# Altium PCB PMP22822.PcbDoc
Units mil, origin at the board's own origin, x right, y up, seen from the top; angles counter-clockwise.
Board outline 2785.43 x 1948.82 mil, 2 copper layers (Top Layer, Bottom Layer), stack 62 mil thick; 55 components, 24 nets, 111 pads, 31 vias.
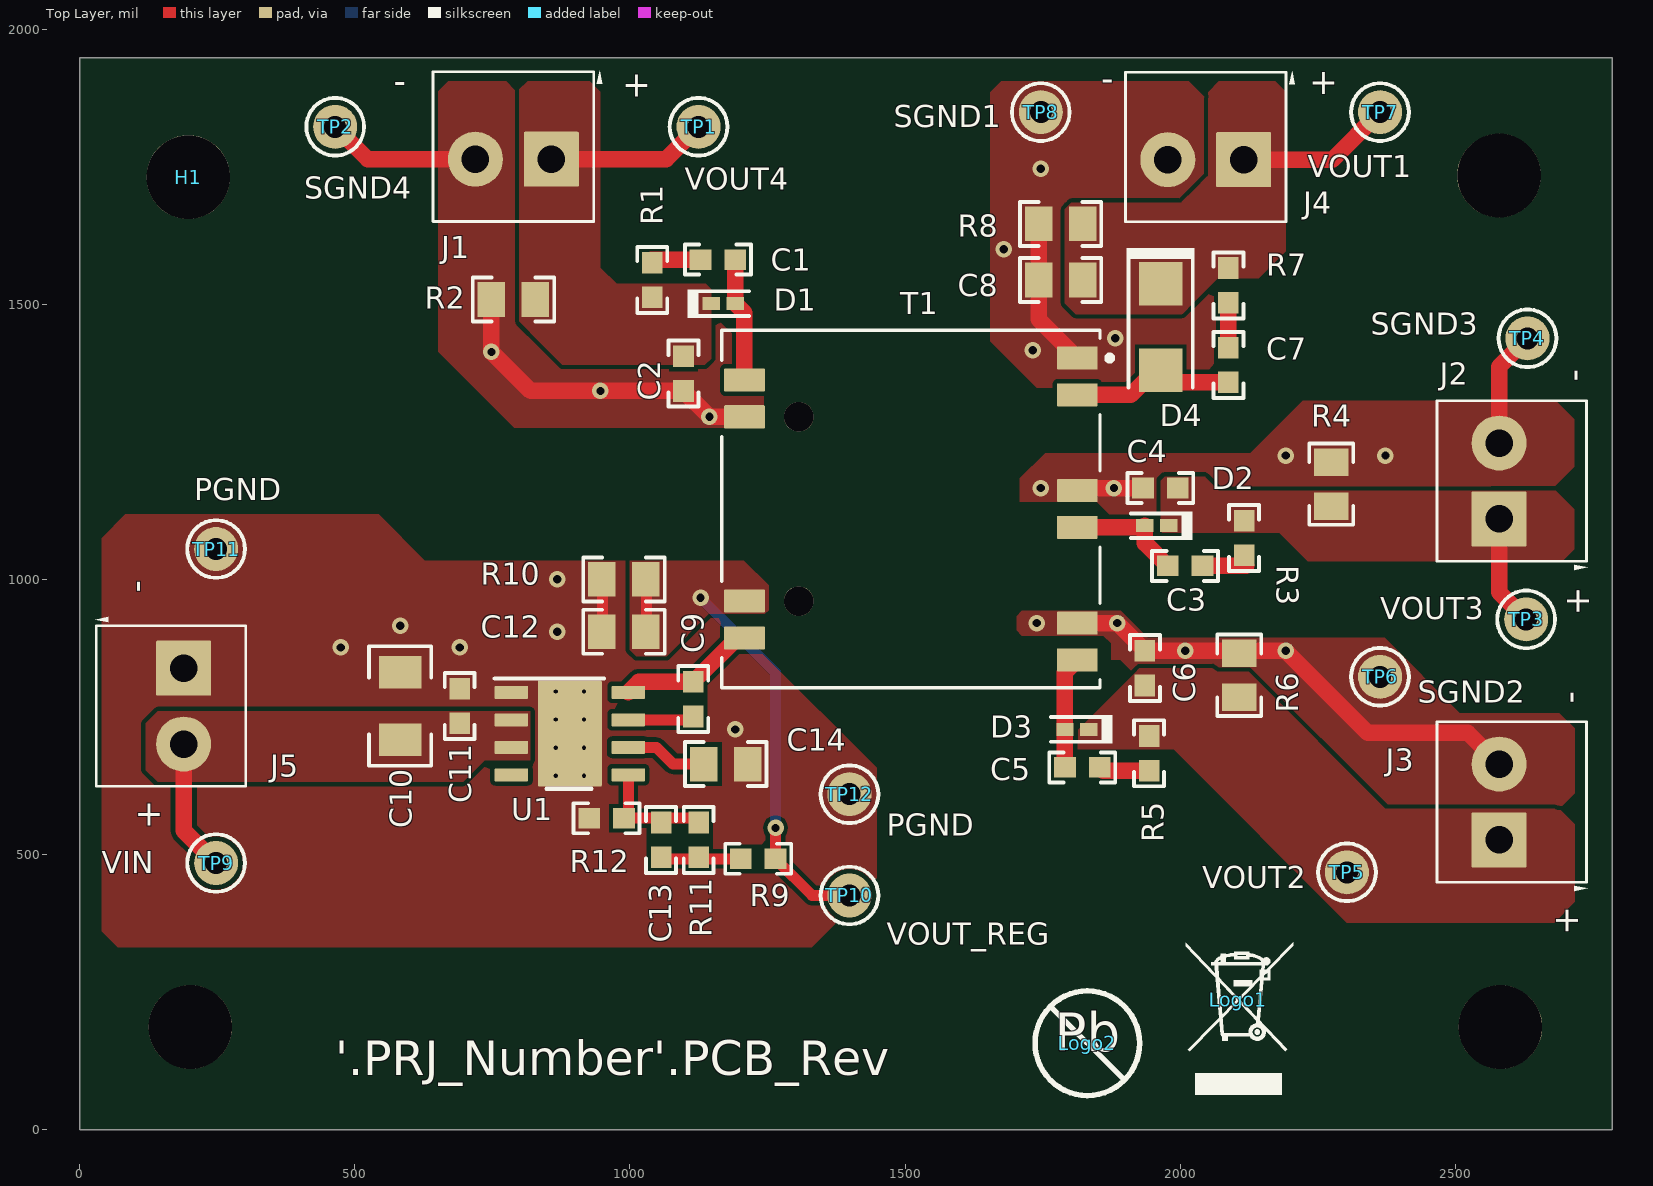
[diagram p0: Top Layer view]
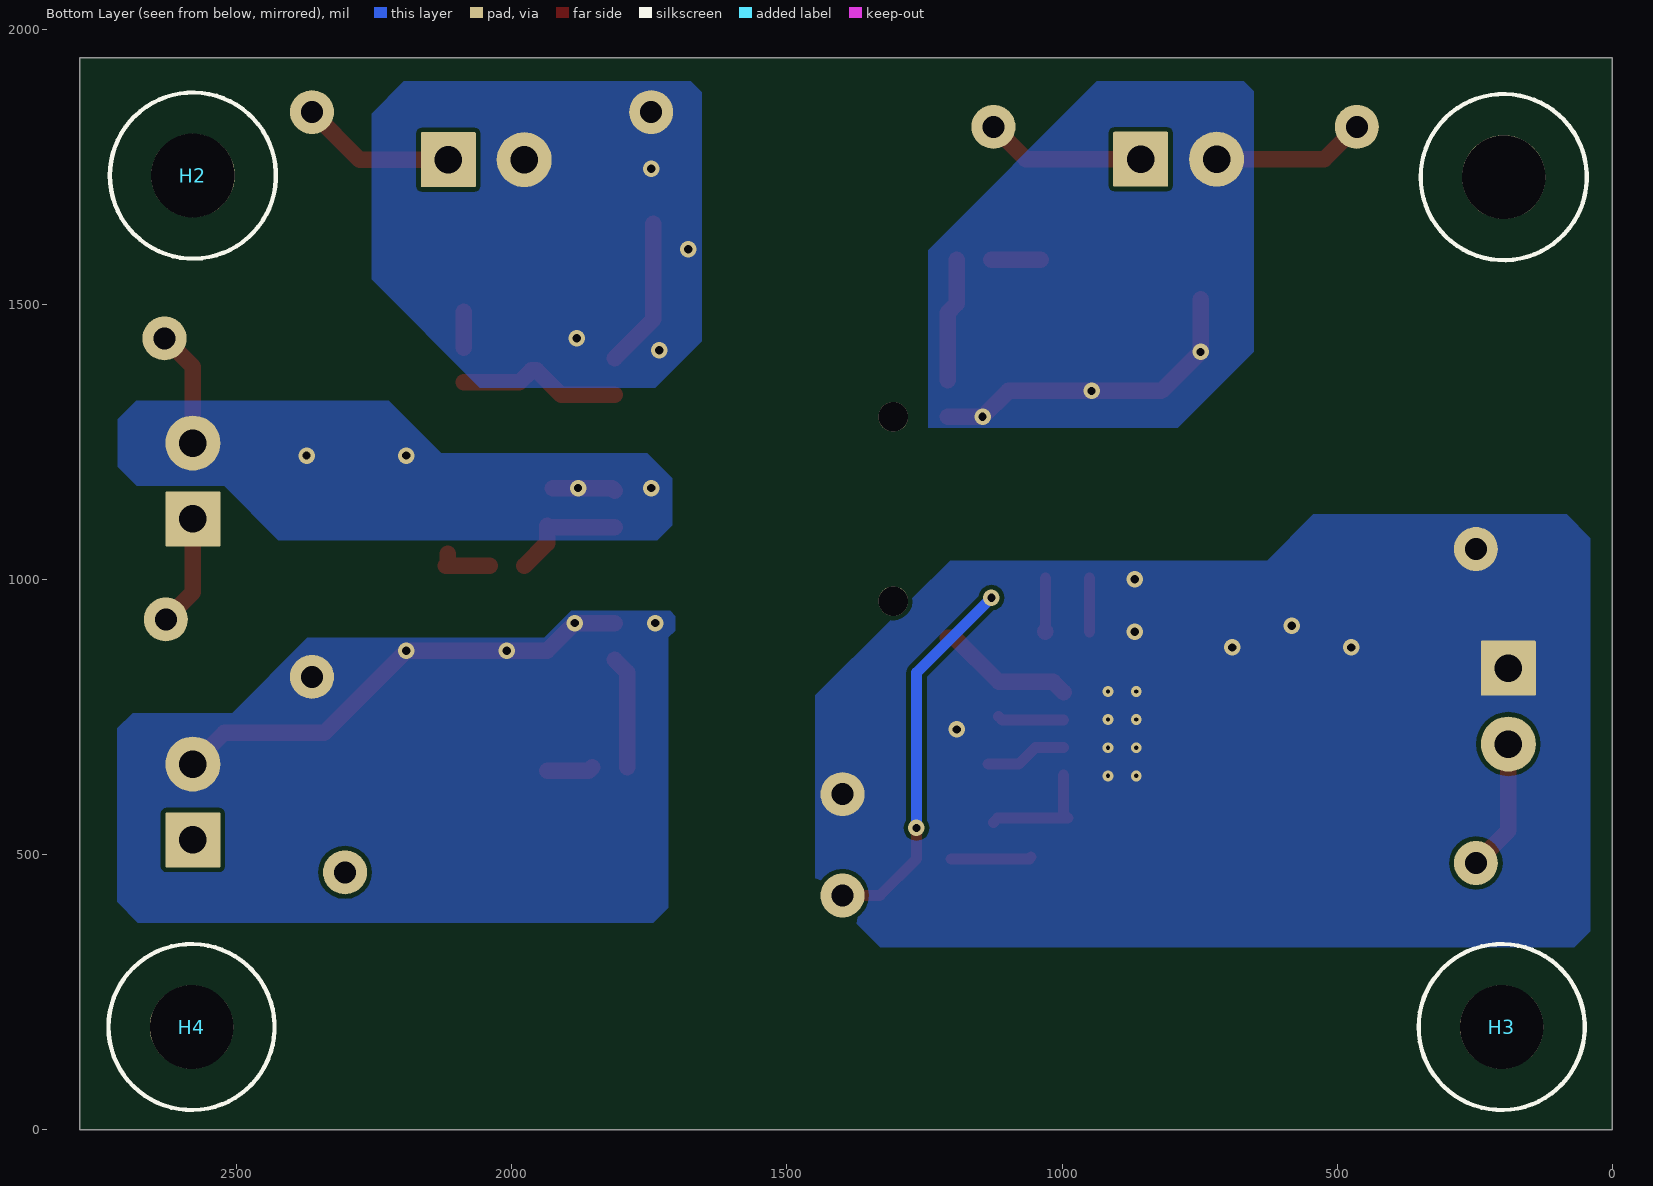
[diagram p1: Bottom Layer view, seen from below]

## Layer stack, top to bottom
Top Solder: solder mask 0.4, Solder Resist, Dk 3.5
Top Layer: signal copper 1.4
Dielectric1: core 59.2, FR-4, Dk 4.8
Bottom Layer: signal copper 1.4
Bottom Solder: solder mask 0.4, Solder Resist, Dk 3.5

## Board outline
0,0 2785.43,0 2785.43,1948.82 0,1948.82

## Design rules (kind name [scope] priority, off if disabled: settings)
AcuteAngle [All] p1: minimum=4.50000000000000E+0001 checktracksonly=FALSE
AssemblyTestPointUsage [All] p1: valid=2
BoardOutlineClearance BoardOutlineClearance_MountingHoles [OnCopper and InComponentClass('Mounting Holes')] p1: gap=25 ignorepadtopadclearanceinfootprint=FALSE
BoardOutlineClearance BoardOutlineClearance_Poly [OnCopper and InPoly] p2: gap=25 ignorepadtopadclearanceinfootprint=FALSE
BoardOutlineClearance [OnCopper and Not InComponentClass('Logo') and not InComponentClass('FiducialMark') and not InRegion(1000,500,4000,800)] p3: gap=25 ignorepadtopadclearanceinfootprint=FALSE
Clearance Clearance_Keepouts [((IsTrack Or IsArc) And Not InPoly) And IsFree and IsKeepOut vs ((IsTrack Or IsArc) And Not InPoly) And IsFree and IsKeepOut] p1: gap=0 ignorepadtopadclearanceinfootprint=FALSE
Clearance Clearance_Poly [InPolygon] p2: gap=8 ignorepadtopadclearanceinfootprint=FALSE except(0: Arc-Hole Track-Hole SMDPad-Hole THPad-Hole Via-Hole Fill-Hole Poly-Hole Region-Hole Text-Hole)
Clearance Clearance_FiducialMark [IsKeepOut and InComponentClass('FiducialMark') vs IsPad and InComponentClass('FiducialMark')] p3: gap=0 ignorepadtopadclearanceinfootprint=FALSE
Clearance [All] p4: gap=7.87 ignorepadtopadclearanceinfootprint=FALSE except(0: Arc-Hole Track-Hole SMDPad-Hole THPad-Hole Via-Hole Fill-Hole Poly-Hole Region-Hole Text-Hole)
ComponentClearance ComponentClearance_MountingHoles_FiducialMarks [InComponentClass('Mounting Holes') vs InComponentClass('FiducialMark')] p1: gap=50 collisioncheckmode=3 verticalgap=10 showdistances=FALSE
ComponentClearance ComponentClearance_Shunt [InComponentClass('Header') vs InComponentClass('Shunt')] p2: gap=0 collisioncheckmode=3 verticalgap=0 showdistances=FALSE
ComponentClearance ComponentClearance_Logo [InComponentClass('Logo')] p3: gap=50 collisioncheckmode=3 verticalgap=10 showdistances=FALSE
ComponentClearance ComponentClearance_ScrewToNut [(HasFootprint('NY PMS 440 0025 PH')) vs (HasFootprint('Keystone_1902C'))] p4: gap=5 collisioncheckmode=3 verticalgap=10 showdistances=FALSE
ComponentClearance ComponentClearance_MountingHoles [InComponentClass('Mounting Holes')] p5: gap=250 collisioncheckmode=3 verticalgap=100000 showdistances=FALSE
ComponentClearance ComponentClearance_SmallPassives [HasFootprint('0201*') or HasFootprint('0402*') or HasFootprint('0508') or HasFootprint('0603*') or HasFootprint('0612') or HasFootprint('0805*') or HasFootprint('0815*') or HasFootprint('0830*') or HasFootprint('1206*') or HasFootprint('1210*') or HasFootprint('1808*') or HasFootprint('1812*') or HasFootprint('1825*') or HasFootprint('2010*') or HasFootprint('2220*') or HasFootprint('2225*') or HasFootprint('2512*') or HasFootprint('2728*') or HasFootprint('3518*') vs HasFootprint('0201*') or HasFootprint('0402*') or HasFootprint('0508') or HasFootprint('0603*') or HasFootprint('0612') or HasFootprint('0805*') or HasFootprint('0815*') or HasFootprint('0830*') or HasFootprint('1206*') or HasFootprint('1210*') or HasFootprint('1808*') or HasFootprint('1812*') or HasFootprint('1825*') or HasFootprint('2010*') or HasFootprint('2220*') or HasFootprint('2225*') or HasFootprint('2512*') or HasFootprint('2728*') or HasFootprint('3518*')] p6: gap=14.96 collisioncheckmode=3 verticalgap=10 showdistances=FALSE
ComponentClearance ComponentClearance_THtoSMT [IsThruComponent vs IsSMTComponent] p7: gap=15 collisioncheckmode=3 verticalgap=30 showdistances=FALSE
ComponentClearance ComponentClearance_THtoTH [IsThruComponent vs IsThruComponent] p8: gap=15 collisioncheckmode=3 verticalgap=30 showdistances=FALSE
ComponentClearance [All] p9: gap=15 collisioncheckmode=3 verticalgap=10 showdistances=FALSE
DiffPairsRouting [All] p1: maxlimit=100 minlimit=10 mostfreqgap=10 toplayer_minwidth=15 toplayer_maxwidth=15 toplayer_prefwidth=15 bottomlayer_minwidth=15 bottomlayer_maxwidth=15 bottomlayer_prefwidth=15 maxuncoupledlength=1000
FabricationTestPointUsage TestPointUsage [All] p1: valid=2 allowmultiple=FALSE
FabricationTestpoint Testpoint [All] p1: side=3 testpointundercomponent=TRUE minsize=40 maxsize=100 preferedsize=60 minholesize=0 maxholesize=40 preferedholesize=32 testpointgrid=1 allowsidetop=TRUE allowsidebottom=TRUE usegrid=TRUE gridtolerance=0.01
FanoutControl Fanout_LCC [IsLCC] p1: bgadir=Out bgaviamode=Centered fanoutstyle=Auto fanoutdirection=Alternating viagrid=1 // Fanout_LCC (Default Rule)
FanoutControl Fanout_BGA [IsBGA] p2: bgadir=Out bgaviamode=Centered fanoutstyle=Auto fanoutdirection=Alternating viagrid=1 // Fanout_BGA (Default Rule)
FanoutControl Fanout_Default [All] p4: bgadir=Out bgaviamode=Centered fanoutstyle=Auto fanoutdirection=Alternating viagrid=1 // Fanout_Default (Default Rule)
FanoutControl Fanout_Small [(CompPinCount < 5)] p5: bgadir=Out bgaviamode=Centered fanoutstyle=Auto fanoutdirection=OutThenIn viagrid=1 // Fanout_Small (Default Rule)
HoleSize [All] p1: absolutevalues=TRUE maxlimit=251 minlimit=7.87 maxpercent=80.000 minpercent=20.000
MinimumAnnularRing MinimumAnnularRing_ThermalPadVias [IsVia and InAnyComponent] p1: minimumring=5.91
MinimumAnnularRing [All] p2: minimumring=7
MinimumSolderMaskSliver MinimumSolderMaskSliver_Logo [InComponentClass('Logo') vs InComponentClass('Logo')] p1: minsoldermaskwidth=0.7
MinimumSolderMaskSliver [All] p2: minsoldermaskwidth=3.94
PlaneConnect [All] p1: planeconnectstyle=Direct reliefexpansion=10 reliefentries=4 reliefconductorwidth=10 reliefairgap=10
PolygonConnect [All] p1: connectstyle=Direct reliefconductorwidth=10 reliefentries=4 polygonreliefangle="90 Angle" airgapwidth=10
RoutingVias ThermalPadVias [IsVia and InAnyComponent] p1: holewidth=7.87 width=19.68 viastyle="Through Hole" minholewidth=7 minwidth=19.68 maxholewidth=12.99 maxwidth=35
RoutingVias [All] p2: holewidth=16 width=34 viastyle="Through Hole" minholewidth=7 minwidth=26 maxholewidth=40 maxwidth=65
SilkToBoardRegionClearance [Not ((IsComment or IsDesignator) And (Hide <> 'False')) and not InRegion(1000,500,4000,800)] p1:
SilkToSilkClearance SilkToSilkClearance_Pb-FreeLogo [(HasFootprint('Pb-Free_Overlay_Medium') OR HasFootprint('Pb-Free_Overlay_Small')) vs (HasFootprint('Pb-Free_Overlay_Medium') OR HasFootprint('Pb-Free_Overlay_Small'))] p1: silktosilkclearance=0
SilkToSilkClearance [All] p2: silktosilkclearance=4
SilkToSolderMaskClearance SilkToComponentPadClearance [IsPad and InAnycomponent] p1: minsilkscreentomaskgap=5 clearancetoexposedcopper=TRUE
SilkToSolderMaskClearance "Silk to Solder Mask Opening" [All] p2: minsilkscreentomaskgap=4 clearancetoexposedcopper=FALSE
SolderMaskExpansion [All] p1: expansion=1.97
Width [All] p1: maxlimit=100 minlimit=6 preferedwidth=10 checkconnectedcopper=TRUE
15 further rules are at their usual default settings.

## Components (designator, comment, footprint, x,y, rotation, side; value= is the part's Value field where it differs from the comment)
C1 "CL10B101KB8NNNC" 0603 1159.79,1582.27 r0 top value=100pF
C2 "C1608X7R1V105K080AC" 0603 1097.33,1374.94 r270 top value=1uF
C3 "CL10B101KB8NNNC" 0603 2009.29,1025.25 r180 top value=100pF
C4 "C1608X7R1V105K080AC" 0603 1964.19,1166.99 r180 top value=1uF
C5 "CL10B101KB8NNNC" 0603 1822.28,659.13 r180 top value=100pF
C6 "C1608X7R1V105K080AC" 0603 1936.16,839.51 r90 top value=1uF
C7 "CL10B101KB8NNNC" 0603 2088.03,1390.69 r270 top value=100pF
C8 "C2012X7R1V225K085AC" 0805_HV 1782.91,1545.22 r180 top value=2.2uF
C9 "C0603X104K3RACTU" 0603 1115.05,783.15 r270 top value=0.1uF
C10 "C3216X7R1H475K160AE" 1206_190M 582.12,770.61 r90 top value=4.7uF
C11 "GRM188R71H224KAC4D" 0603 690.39,770.61 r90 top value=0.22uF
C12 "C2012X7R1V475K125AC" 0805_HV 989.06,905.64 r180 top value=4.7uF
C13 "CL10B101KB8NNNC" 0603 1056.56,527.24 r90 top value=100pF
C14 "GRM21BR71C105KA01L" 0805_HV 1174.1,665.04 r0 top value=1uF
D1 "RB520SM-40FH" SOD-523 1169.63,1502.27 r0 top value=45V
D2 "RB520SM-40FH" SOD-523 1957.82,1098.45 r180 top value=45V
D3 "RB520SM-40FH" SOD-523 1812.44,728.03 r180 top value=45V
D4 "B150-13-F" SMA 1964.71,1459.59 r270 top value=50V
H1 "4824" KEYSTONE_4824 196.85,1732.28 r0 top
H2 "4824" KEYSTONE_4824 2580.15,1735.07 r180 bottom
H3 "4824" KEYSTONE_4824 200.66,187.01 r180 bottom
H4 "4824" KEYSTONE_4824 2582.55,187.01 r180 bottom
J1 "ED555/2DS" TERM_BLK_ED555-2DS 856.93,1764.71 r180 top
J2 "ED555/2DS" TERM_BLK_ED555-2DS 2580.15,1110.75 r90 top
J3 "ED555/2DS" TERM_BLK_ED555-2DS 2580.15,527.04 r90 top
J4 "ED555/2DS" TERM_BLK_ED555-2DS 2115.79,1763.91 r180 top
J5 "ED555/2DS" TERM_BLK_ED555-2DS 188.42,839.51 r270 top
Logo1 "WEEE logo" WEEE_Minimum 2106.3,236.22 r0 top
Logo2 "Pb-Free Symbol" Pb-Free_Overlay_Medium 1831.53,157.48 r0 top
R1 "RC0603FR-07200RL" 0603 1040.33,1545.28 r270 top value=200
R2 "MCU08050C1002FP500" 0805_HV 788.18,1509.79 r0 top value=10.0k
R3 "RC0603FR-07200RL" 0603 2116.57,1075.95 r90 top value=200
R4 "MCU08050C1002FP500" 0805_HV 2275.03,1174.16 r270 top value=10.0k
R5 "RC0603FR-07200RL" 0603 1943.68,684.72 r90 top value=200
R6 "MCU08050C1002FP500" 0805_HV 2107.71,826.32 r270 top value=10.0k
R7 "RC0603FR-07200RL" 0603 2088.03,1535.43 r90 top value=200
R8 "MCU08050C1002FP500" 0805_HV 1782.91,1647.22 r0 top value=10.0k
R9 "RMCF0603ZT0R00" 0603 1233.16,492.79 r0 top value=0
R10 "MCU08050C1002FP500" 0805_HV 989.06,1000.93 r0 top value=10.0k
R11 "RC0603FR-07100KL" 0603 1124.89,527.24 r90 top value=100k
R12 "RC0603FR-076K2L" 0603 957.57,566.61 r0 top value=6.20k
T1 "750319519" FP-750319519_SMT_XFRMR_17MM46_16MM51-MFG 1510.72,1128.88 r0 top
TP1 "VOUT4" Keystone5000 1124.63,1823.76 r90 top
TP2 "SGND4" Keystone5001 464.04,1823.76 r90 top
TP3 "VOUT3" Keystone5000 2629.37,928.09 r90 top
TP4 "SGND3" Keystone5001 2631.76,1439.12 r90 top
TP5 "VOUT2" Keystone5000 2303.58,468.29 r90 top
TP6 "SGND2" Keystone5001 2363.65,823.76 r90 top
TP7 "VOUT1" Keystone5000 2363.62,1850.39 r90 top
TP8 "SGND1" Keystone5001 1746.83,1850.39 r90 top
TP9 "VIN" Keystone5000 247.48,485.18 r90 top
TP10 "VOUT_REG" Keystone5000 1399.05,426.12 r180 top
TP11 "PGND" Keystone5001 247.48,1056.05 r90 top
TP12 "PGND" Keystone5001 1399.05,610.24 r180 top
U1 "LMR36520ADDA" DDA0008J 890.64,720.35 r0 top

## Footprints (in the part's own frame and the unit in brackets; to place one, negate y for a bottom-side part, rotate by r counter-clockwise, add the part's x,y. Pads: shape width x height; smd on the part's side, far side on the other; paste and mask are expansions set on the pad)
0603 [mm] "0603 from SM-752 data"
  rect 1x0.95 smd: 1(-0.8,0) 2(0.8,0)
  silkscreen extent -1.52,-0.69 1.52,0.69, body extent -0.87,-0.47 0.87,0.47, height 1
0805_HV [mil] "0805 with 30mil clearance between pads"
  rect 50x63 smd: 1(-40,0) 2(40,0)
  silkscreen extent -74,-40 74,40, body extent -43,-29 43,29, height 57
1206_190M [mm] "1206_190"
  rect 1.5x1.95 smd: 1(-1.55,0) 2(1.55,0)
  silkscreen extent -2.76,-1.44 2.76,1.44, body extent -1.75,-0.95 1.75,0.95, height 1.9
DDA0008J [mm] "SOIC, 8-Leads, Body 4.9x3.9mm, Pitch 1.27mm, Exposed Pad"
  rrect14% 1.55x0.6 smd: 1(-2.7,1.905) 2(-2.7,0.635) 3(-2.7,-0.635) 4(-2.7,-1.905) 5(2.7,-1.905) 6(2.7,-0.635) 7(2.7,0.635) 8(2.7,1.905)
  rrect4% 2.95x4.9 smd paste-1.5 mask-1.5: 9(0,0)
  silkscreen extent -3.47,-2.55 1.58,2.55, body extent -3.01,-2.45 3.01,2.45, height 1.57
FP-750319519_SMT_XFRMR_17MM46_16MM51-MFG [mm]
  rrect9% 1.88x1.07 smd paste+0 mask+0: 1(7.685,6.97) 2(7.685,5.27) 4(7.685,0.85) 5(7.685,-0.85) 7(7.685,-5.27) 8(7.685,-6.97) 9(-7.685,-5.955) 10(-7.685,-4.255) 15(-7.685,4.255) 16(-7.685,5.955)
  round 1.37 hole 1.37 unplated paste-1000 mask+0: ""(-5.18,-4.255) ""(-5.18,4.255)
  silkscreen extent -8.73,-8.25 9.31,8.25, body extent -8.83,-8.35 8.83,8.35, height 0.25
Keystone5000 [mil] "For Keystone 500x miniature loop terminals"
  round 80 hole 40: 1(0,0)
  silkscreen extent -52,-52 52,52, body extent -49,-49 49,49, height 182
Keystone5001 [mil] "For Keystone 500x miniature loop terminals"
  round 80 hole 40: 1(0,0)
  silkscreen extent -52,-52 52,52, body extent -49,-49 49,49, height 182
KEYSTONE_4824 [mil] "HEX STANDOFF 6-32 NYLON 1-1/2\""
  round 1 on Mech4: 0(0,0)
  round 152 hole 152 unplated: MH(0,0)
  body extent -144,-125 144,125, height 1500
Pb-Free_Overlay_Medium [mil]
  silkscreen extent -95,-95 95,95
SMA [mm] "Molded Diode, 2-Leads, Body 4.3x2.6mm, IPC Medium Density, based on OnSemi component dimensions and land pattern"
  rect 2x2 smd: 1(-2,0) 2(2,0)
  silkscreen extent -3.66,-1.57 2.79,1.57, body extent -2.6,-1.3 2.6,1.3, height 2.42
SOD-523 [mm] "NXP Semiconductor recommended land pattern, nominal STEP model"
  rect 0.8x0.6 smd paste-0.05: 1(-0.55,0) 2(0.55,0)
  silkscreen extent -1.65,-0.66 1.2,0.66, body extent -0.8,-0.4 0.8,0.4, height 0.72
TERM_BLK_ED555-2DS [mil]
  rrect4% 100x100 hole 50: 1(0,0)
  round 100 hole 50: 2(138,0)
  silkscreen extent -93,-161 215,113, body extent -69,-150 207,106, height 323
WEEE_Minimum [mil] "WEEElie bin"
  silkscreen extent -95,-172 99,104

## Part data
C1 C3 C5 C7 C13: library part CMP-0083857-1, "CAP, CERM, 100 pF, 50 V,+/- 10%, X7R, 0603", Cap_Case=0603, Manufacturer="Samsung Electro-Mechanics", TempCo=X7R, Tolerance_%=10%, Value2=50V, ValueDisplayed=100pF
C2 C4 C6: library part CMP-0007052-4, "CAP, CERM, 1 uF, 35 V, +/- 10%, X7R, 0603", Cap_Case=0603, Manufacturer=TDK, Supplier Part Number 1=445-7414-1-ND, TempCo=X7R, Tolerance_%=10%, Value1=Unknown, Value2=35V, ValueDisplayed=1uF
C8: library part CMP-0007883-2, "CAP, CERM, 2.2 uF, 35 V, +/- 10%, X7R, 0805", Cap_Case=0805, Manufacturer=TDK, Supplier Part Number 1=445-14547-1-ND, TempCo=X7R, Tolerance_%=10%, Value1=Unknown, Value2=35V, ValueDisplayed=2.2uF
C9: library part CMP-0006979-5, "CAP, CERM, 0.1 uF, 25 V, +/- 10%, X7R, 0603", Cap_Case=0603, Manufacturer=Kemet, Supplier Part Number 1=399-5345-1-ND, TempCo=X7R, Tolerance_%=10%, Value1=Unknown, Value2=25V, ValueDisplayed=0.1uF
C10: library part CMP-0082522-1, "CAP, CERM, 4.7 µF, 50 V,+/- 10%, X7R, 1206", Cap_Case=1206, Manufacturer=TDK, Supplier Part Number 1=445-172491-1-ND, TempCo=X7R, Tolerance_%=10%, Value2=50V, ValueDisplayed=4.7µF
C11: library part CMP-0007445-4, "CAP, CERM, 0.22 uF, 50 V, +/- 10%, X7R, 0603", Cap_Case=0603, Manufacturer=MuRata, Supplier Part Number 1=490-12546-1-ND, TempCo=X7R, Tolerance_%=10%, Value1=Unknown, Value2=50V, ValueDisplayed=0.22uF
C12: library part CMP-0007885-2, "CAP, CERM, 4.7 uF, 35 V, +/- 10%, X7R, 0805", Cap_Case=0805, Manufacturer=TDK, Supplier Part Number 1=445-7555-1-ND, TempCo=X7R, Tolerance_%=10%, Value1="0.002346 ohm", Value2=35V, ValueDisplayed=4.7uF
C14: library part CMP-0008323-2, "CAP, CERM, 1 uF, 16 V, +/- 10%, X7R, 0805", Cap_Case=0805, Manufacturer=MuRata, Supplier Part Number 1=490-1691-1-ND, TempCo=X7R, Tolerance_%=10%, Value1="0.003 ohm", Value2=16V, ValueDisplayed=1uF
D1 D2 D3: library part CMP-0077062-3, "Diode, Schottky, 45 V, 0.2 A, AEC-Q101, SOD-523", Manufacturer=Rohm, Value1=0.2A, Value2=0.55V
D4: library part CMP-0028387-2, "Diode, Schottky, 50 V, 1 A, SMA", Manufacturer="Diodes Inc.", Value1=1A, Value2=0.7V
H1 H2 H3 H4: library part CMP-0003690-1, Manufacturer=Keystone, Supplier Part Number 1=36-4824-ND
J1 J2 J3 J4 J5: library part CMP-0074913-1, "Terminal Block, 3.5mm Pitch, 2x1, TH", Color=Grey, Current_A=6A, Manufacturer="On-Shore Technology", Supplier Part Number 1=ED1514-ND, Voltage_V=150V
Logo1: library part CMP-0074769-1
Logo2: library part CMP-0074839-1
R1 R3 R5 R7: library part CMP-0022902-5, "RES, 200, 1%, 0.1 W, 0603", Manufacturer=Yageo, Power_W=100mW, Supplier Part Number 1=311-200HRCT-ND, TempCo="100 ppm/C", Tolerance_%=1%, Value2=0.1W, Value_Code=200R, ValueDisplayed=200
R2 R4 R6 R8 R10: library part CMP-0021857-2, "RES, 10.0 k, 1%, 0.2 W, 0805", Manufacturer=Vishay/Beyschlag, Power_W=200mW, Supplier Part Number 1=MCU0805-10.0K-CFCT-ND, TempCo="50 ppm/C", Tolerance_%=1%, Value2=0.2W, Value_Code=10k0, ValueDisplayed=10.0k
R9: library part CMP-0023343-3, "RES, 0, 1%, 0.1 W, AEC-Q200 Grade 0, 0603", Manufacturer="Stackpole Electronics Inc", Power_W=100mW, Supplier Part Number 1=RMCF0603ZT0R00CT-ND, TempCo=ppm/C, Tolerance_%=1%, Value2=0.1W, Value_Code=0
R11: library part CMP-0022735-5, "RES, 100 k, 1%, 0.1 W, 0603", Manufacturer=Yageo, Power_W=100mW, Supplier Part Number 1=311-100KHRCT-ND, TempCo="100 ppm/C", Tolerance_%=1%, Value2=0.1W, Value_Code=100k
R12: library part CMP-0023248-5, "RES, 6.20 k, 1%, 0.1 W, 0603", Manufacturer=Yageo, Power_W=100mW, Supplier Part Number 1=311-6.20KHRCT-ND, TempCo="100 ppm/C", Tolerance_%=1%, Value2=0.1W, Value_Code=6k20, ValueDisplayed=6.20k
T1: library part CMP-0091384-1, "Tranformer, 0.15Ohm PRI, 0.35Ohm SEC, 42.5uH, 1:1:1:1:1, 4000VAC, 17.46x16.51x12.70mm SMT", Frequency_Fixed=400kHz, Manufacturer="Wurth Electronics", Operating Temperature Range="-40°C to +125°C", Voltage_Isolation_Vrms=4kV
TP1 TP3 TP5 TP7 TP9 TP10: library part CMP-0055137-1, "Test Point, Miniature, Red, TH", Color=Red, Manufacturer=Keystone, PartNumber=5000, Supplier Part Number 1=36-5000-ND
TP2 TP4 TP6 TP8 TP11 TP12: library part CMP-0055138-1, "Test Point, Miniature, Black, TH", Color=Black, Manufacturer=Keystone, PartNumber=5001, Supplier Part Number 1=36-5001-ND
U1: library part CMP-0860813-1, "SIMPLE SWITCHER® 4.2-V to 65-V, 2-A Synchronous Step-down Converter, DDA0008J (HSOIC-8)", Alternate Manufacturer="Texas Instruments"

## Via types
v1: diameter 30, hole 15, Top Layer to Bottom Layer, 21 vias
v2: diameter 19.68, hole 7.87, Top Layer to Bottom Layer, tented both sides, 4 vias
v3: diameter 19.68, hole 7.87, Top Layer to Bottom Layer, 4 vias
v4: diameter 30, hole 15, Top Layer to Bottom Layer, tented top, 2 vias

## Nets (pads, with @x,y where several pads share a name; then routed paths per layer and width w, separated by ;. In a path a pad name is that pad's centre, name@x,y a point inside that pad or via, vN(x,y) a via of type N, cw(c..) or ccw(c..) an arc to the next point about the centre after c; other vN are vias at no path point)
GND: C10.2 C11.2 C12.2 C14.2 J5.1 R10.1 R12.1 TP11.1 TP12.1 U1.1 U1.9 | length 98.2
  Top Layer w20: C12.2@949.6,905.64 950.02,906.05 R10.1@950.02,1003.65
  other v1: 1191.29,728.03 473.89,877.09 690.39,877.09 867.59,905.64 582.12,916.51 867.55,1000.93
  other v2: 865.05,643.58 916.23,643.58 865.05,797.12 916.23,797.12
  other v3: 865.05,694.76 916.23,694.76 865.05,745.94 916.23,745.94
NetC1_1: C1.1 R1.1 | length 90
  Top Layer w30: R1.1@1038.28,1582.27 C1.1
NetC1_2: C1.2 D1.2 T1.16 | length 225.9
  Top Layer w30: C1.2 D1.2 1208.16,1485.39 T1.16
NetC2_1: C2.1 D1.1 J1.1 R1.2 R2.2 TP1.1 | length 292.2
  Top Layer w30: J1.1 1065.58,1764.71 TP1.1
NetC3_1: C3.1 R3.1 | length 102.1
  Top Layer w30: C3.1 R3.1@2116.57,1025.25 ; R3.1@2116.57,1047.9 R3.1@2116.57,1025.25 ; R3.1@2120.2,1025.25 R3.1@2116.57,1025.25
NetC3_2: C3.2 D2.2 T1.5 | length 214.6
  Top Layer w30: T1.5 1933.13,1095.42 D2.2 1936.16,1066.88 C3.2
NetC4_1: C4.1 D2.1 J2.1 R3.2 R4.2 TP3.1 | length 203
  Top Layer w30: J2.1 2580.15,977.31 TP3.1
NetC5_1: C5.1 R5.1 | length 84.9
  Top Layer w30: C5.1 1860.4,652.5 R5.1@1935.9,652.5
NetC5_2: C5.2 D3.2 T1.8 | length 204.7
  Top Layer w30: C5.2 D3.2 1790.78,831.97 T1.8
NetC6_1: C6.1 D3.1 J3.1 R5.2 R6.2 TP5.1
NetC7_1: C7.1 R7.1 | length 65
  Top Layer w30: C7.1 R7.1@2088.03,1487.14
NetC7_2: C7.2 D4.2 T1.2 | length 302.1
  Top Layer w30: T1.2 1910.38,1336.36 1954.87,1380.85 D4.2 1986.36,1359.2 C7.2
NetC8_1: C8.1 D4.1 J4.1 R7.2 R8.2 TP7.1 | length 283.6
  Top Layer w30: J4.1 2277.14,1763.91 TP7.1
NetC9_1: C9.1 T1.9 U1.8 | length 252.3
  Top Layer w30: U1.8 1016.23,814.64 C9.1 1194.84,894.43 T1.9
NetC9_2: C9.2 U1.7 | length 120.7
  Top Layer w20: U1.7 1108.75,745.35 C9.2
NetC10_1: C10.1 C11.1 J5.2 TP9.1 U1.2 U1.3 | length 240.8
  Top Layer w30: J5.2 188.42,544.23 TP9.1
NetC12_1: C12.1 R9.2 R10.2 T1.10 TP10.1 | length 792.6
  Top Layer w20: C12.1@1029.6,905.64 1030.02,906.05 R10.2@1030.02,1003.65 ; v1(1264.65,548.9) R9.2 1331.32,426.12 TP10.1
  Top Layer w30: C12.1@1030.02,906.05 C12.1@1030.91,906.94
  Bottom Layer w20: v1(1128.29,967.46) 1264.65,831.1 v1(1264.65,548.9)
NetC13_1: C13.1 R9.1 R11.1 | length 146.3
  Top Layer w20: C13.1 1059.52,492.79 R9.1
NetC13_2: C13.2 R11.2 R12.2 U1.5 | length 221.1
  Top Layer w20: U1.5 996.94,574.49 R12.2 1117.02,566.61 R11.2
NetC14_1: C14.1 U1.6 | length 149.7
  Top Layer w20: U1.6 1047.93,695.35 1078.24,665.04 C14.1
SGND1: C8.2 J4.2 R8.1 T1.1 TP8.1 | length 273.1
  Top Layer w30: R8.1 C8.2 1742.91,1473.66 T1.1
  other v1: 1732.28,1417.32 1679.32,1600.97 1746.83,1747.58
  other v4: 1882.26,1439.12
SGND2: C6.2 J3.2 R6.1 T1.7 TP6.1 | length 873.1
  Top Layer w30: T1.7 v1(1885.77,921.4) C6.2 v1(2192.03,871.01) 2341.01,722.03 2523.16,722.03 J3.2
  other v1: 2009.32,871.01 1739.6,921.4
SGND3: C4.2 J2.2 R4.1 T1.4 TP4.1 | length 326.7
  Top Layer w30: T1.4 1817.92,1166.99 C4.2@1926.32,1166.99 ; J2.2 2580.15,1387.51 TP4.1
  other v1: 1746.83,1166.99 2192.03,1226.05 2373.46,1226.05
  other v4: 1879.92,1166.99
SGND4: C2.2 J1.2 R2.1 T1.15 TP2.1 | length 883.6
  Top Layer w30: TP2.1 523.1,1764.71 J1.2 ; R2.1 v1(748.15,1414.39) 819.13,1343.45 C2.2 1144.38,1296.4 T1.15
  other v1: 1144.35,1296.4 946.33,1343.45
pads on no net: H1.0 H1.MH H2.0 H2.MH H3.0 H3.MH H4.0 H4.MH T1. U1.4

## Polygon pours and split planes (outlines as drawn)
SGND1 on Top Layer "TOP_LAYER_SGND1_P022" (solid, remove dead copper, pour order 22): 1739.4,1349.59 2058.21,1349.59 2255.38,1546.76 2255.38,1667.16 2016.1,1906.44 1674.67,1906.44 1654.99,1886.75 1654.99,1434
SGND3 on Top Layer "TOP_LAYER_SGND3_P030" (solid, remove dead copper, pour order 30): 2682.42,1171.26 2716.54,1205.38 2716.54,1292.27 2683.05,1325.75 2627.95,1325.73 2223.44,1325.73 2127.89,1230.18 2001.41,1230.32 1941.66,1230.32 1754.58,1230.31 1708.91,1184.64 1708.91,1141.87 1848.39,1141.71 1871.88,1118.22 1871.88,1072.45 2466.94,1072.45 2565.75,1171.26
SGND2 on Top Layer "TOP_LAYER_SGND2_P026" (solid, remove dead copper, pour order 26): 1712.6,943.83 1703,934.23 1703,929.47 1703,908.18 1712.2,898.42 1860.66,898.42 1874.59,884.49 1874.59,854.47 1891.41,854.47 2165.17,580.71 2687.01,580.71 2717.95,611.65 2717.95,729.83 2689.9,757.87 2508.57,757.87 2372.01,894.43 1941.37,894.43 1891.97,943.83
SGND4 on Top Layer "TOP_LAYER_SGND4_P020" (solid, remove dead copper, pour order 20): 651.05,1843.45 651.05,1888.2 669.29,1906.44 774.6,1906.44 790.5,1890.54 790.5,1842.65 1243.27,1389.88 1243.27,1276.52 789.5,1276.52 651.05,1414.96
GND on Top Layer "TOP_LAYER_GND_P014" (solid, remove dead copper, pour order 14): 39.42,1075.95 82.51,1119.04 542.78,1119.04 626.71,1035.12 1071.18,1035.12 1448.3,658 1448.3,449.75 1330.19,331.64 68.95,331.64 39.42,361.16
NetC8_1 on Top Layer "TOP_LAYER_NETC8_1_P012" (solid, remove dead copper, pour order 12): 2051.21,1886.93 2070.72,1906.44 2173.32,1906.44 2192.03,1887.72 2192.03,1597.38 2142.82,1548.17 2069.04,1548.17 2004.08,1483.21 1809.84,1483.21 1790.78,1502.27 1790.78,1674.16 1802.59,1685.97 2002.11,1685.97 2051.21,1735.07
NetC4_1 on Top Layer "TOP_LAYER_NETC4_1_P010" (solid, remove dead copper, pour order 10): 2649.05,1033.75 2694.86,1033.75 2717.15,1056.05 2717.15,1127.99 2682.8,1162.34 2070.67,1162.34 2045.18,1187.83 1970.65,1187.83 1964.71,1181.89 1964.71,1088.34 1967.48,1085.57 2180.15,1085.57 2231.98,1033.75
NetC10_1 on Top Layer "TOP_LAYER_NETC10_1_P008" (solid, remove dead copper, pour order 8): 818.34,760.77 141.44,760.77 119.52,738.86 119.52,654.24 140.95,632.82 696.55,632.82 735.92,672.19 818.34,672.19
NetC12_1 on Top Layer "TOP_LAYER_NETC12_1_P006" (solid, remove dead copper, pour order 6): 1245.33,937.94 1251.86,944.47 1251.86,989.84 1206.58,1035.12 999.89,1035.12 999.89,872.71 1011.44,861.16 1066.37,861.16 1143.14,937.94
NetC2_1 on Top Layer "TOP_LAYER_NETC2_1_P004" (solid, remove dead copper, pour order 4): 798.66,1843.45 798.88,1891.54 813.77,1906.44 927.1,1906.44 946.29,1887.24 946.29,1567.86 975.82,1538.33 1138.14,1538.33 1147.98,1528.49 1147.98,1444.74 1147.98,1402.95 1135.72,1390.69 877.4,1390.69 798.66,1469.43
NetC6_1 on Top Layer "TOP_LAYER_NETC6_1_P000" (solid, remove dead copper, pour order 0): 1988.59,691.87 2303.55,376.91 2680.06,376.91 2717.95,414.8 2717.95,555.36 2689.7,583.6 2374.09,583.6 2118.18,839.51 1926.87,839.51 1812.43,725.07 1812.43,691.87
SGND1 on Bottom Layer "BOTTOM_LAYER_SGND1_P032" (solid, remove dead copper, pour order 32): 1739.4,1349.59 2058.21,1349.59 2255.38,1546.76 2255.38,1847.38 2196.33,1906.44 1674.67,1906.44 1654.99,1886.75 1654.99,1434
SGND2 on Bottom Layer "BOTTOM_LAYER_SGND2_P028" (solid, remove dead copper, pour order 28): 1712.6,943.83 1703,934.23 1703,907.9 1715.63,895.27 1715.63,404.19 1742.91,376.91 2680.06,376.91 2717.95,414.8 2717.95,729.83 2689.9,757.87 2508.57,757.87 2372.01,894.43 1941.37,894.43 1891.97,943.83 1732.28,943.83
SGND3 on Bottom Layer "BOTTOM_LAYER_SGND3_P024" (solid, remove dead copper, pour order 24): 2683.07,1325.73 2716.54,1292.27 2716.54,1205.38 2682.42,1171.26 2523.59,1171.26 2424.77,1072.45 1735.57,1072.45 1708.91,1099.11 1708.91,1184.64 1754.45,1230.18 2128.6,1230.18 2224.16,1325.73
SGND4 on Bottom Layer "BOTTOM_LAYER_SGND4_P018" (solid, remove dead copper, pour order 18): 936.45,1906.44 1243.42,1599.47 1243.27,1595.42 1243.27,1276.52 789.5,1276.52 651.05,1414.96 651.05,1888.2 669.29,1906.44
GND on Bottom Layer "BOTTOM_LAYER_GND_P016" (solid, remove dead copper, pour order 16): 39.42,1075.95 82.51,1119.04 542.78,1119.04 626.71,1035.12 1203.19,1035.12 1448.3,790.01 1448.3,449.75 1330.19,331.64 68.95,331.64 39.42,361.16

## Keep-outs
Keep-Out Layer:
  text ".Layer_Name" at 577,-858.49 h60

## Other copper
Top Layer:
  text ".Layer_Name" at 577,-858.49 h60
Bottom Layer:
  text ".Layer_Name" at 577,-858.49 h60

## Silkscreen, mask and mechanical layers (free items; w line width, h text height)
Top Overlay:
  text "-" at 1856.91,1874.61 h78.74
  text "-" at 570.87,1870.08 h78.74
  text "+" at 2235.03,1867.07 h78.74
  text "+" at 985.66,1863.13 h78.74
  text "-" at 2688.97,1382.82 h78.74 r270
  text "+" at 2688.42,987.15 h78.74 r270
  text "-" at 138.31,976.44 h78.74 r90
  text "-" at 2681.21,797.24 h78.74 r270
  text "+" at 99.84,537.68 h78.74
  text "+" at 2668.74,406.44 h78.74 r270
  text "'.PRJ_Number'.PCB_Rev" at 464.04,78.74 h108.27
  text ".Layer_Name" at 577,-858.49 h60
Bottom Overlay:
  text ".Layer_Name" at 577,-858.49 h60
Top Paste:
  text ".Layer_Name" at 577,-858.49 h60
Bottom Paste:
  text ".Layer_Name" at 577,-858.49 h60
Top Solder:
  text ".Layer_Name" at 577,-858.49 h60
  text ".Layer_Name" at 577,-858.49 h60
Bottom Solder:
  text ".Layer_Name" at 577,-858.49 h60
Drill Guide:
  text ".Layer_Name" at 577,-858.49 h60
M1 Board Outline:
  the board outline again, w10
  text ".Layer_Name" at 577,-858.49 h60
M2 Board Dimensions:
  rectangle: 0,-275 125,-150
  rectangle: 125,-400 500,-275
  lines w7: 0,-275 1000,-275 ; 125,-400 125,-150 ; 250,-400 250,-150 ; 500,-400 500,-150 ; 750,-400 750,-150 ; 0,-400 1000,-400 1000,-150 0,-150 0,-400
  text ".Layer_Name" at 577,-858.49 h60
M3 3D STEP Top:
  text ".Layer_Name" at 577,-858.49 h60
M4 3D STEP Bottom:
  text ".Layer_Name" at 577,-858.49 h60
M5 Assembly Top:
  lines w10: -292,-930.17 6308,-930.17 ; -292,-726.83 6310,-726.83 ; -292,-523.5 -292,-1133.5 3713,-1133.5 6310,-1133.5 6310,-523.5 -291.5,-523.5 -291.5,-1133.5 1284,-1133.5 ; 2173,-1133.5 2173,-523.5 ; 3440,-726.83 3440,-523.5 ; 4280,-726.83 4280,-523.5 ; 4902,-1140 4902,-937.17
  text "COMPONENTS MARKED 'DNP' SHOULD NOT BE POPULATED." at 1153.5,-318.5 h60
  text "ASSEMBLY VARIANT:" at 1153,-434 h60
  text ".VariantName" at 2189,-434 h60
  text "PCB VIEWED FROM TOP SIDE" at -228.5,-655.67 h60
  text "BOARD #:" at 2248,-655.67 h60
  text ".PRJ_Number" at 2793.5,-655.67 h60
  text "REV:" at 3638,-655.67 h60
  text ".PCB_Rev" at 3929.5,-655.67 h60
  text "SVN REV:" at 4476,-655.67 h60
  text ".VersionControl_RevNumber" at 4982,-655.67 h60
  text "TID #:" at 2248,-859 h60
  text ".TID" at 2793.5,-859 h60
  text "PLOT NAME =" at -228.5,-1064.34 h60
  text ".plot_File_Name" at 577,-1064.34 h60
  text "GENERATED    :" at 2250,-1064.34 h60
  text ".Print_Date" at 3119.5,-1064.34 h60
  text ".Print_Time" at 3848.5,-1064.34 h60
  text "TEXAS INSTRUMENTS" at 5113,-1064.34 h60
M6 Assembly Bottom:
  lines w10: -292.5,-727.33 6309.5,-727.33 ; -290.5,-930.67 6309.5,-930.67 ; 1115.5,-1140.5 1115.5,-937.67 ; 1737.5,-727.33 1737.5,-524 ; 2577.5,-727.33 2577.5,-524 ; 3844.5,-1134 3844.5,-524 ; 4733.5,-1134 6309,-1134 6309,-524 -292.5,-524 -292.5,-1134 2304.5,-1134 6309.5,-1134 6309.5,-524
  text "COMPONENTS MARKED 'DNP' SHOULD NOT BE POPULATED." at 6102,-318 h60
  text ".VariantName" at 5058,-434 h60
  text "ASSEMBLY VARIANT:" at 6097,-434 h60
  text ".VersionControl_RevNumber" at 1035.5,-656.17 h60
  text "SVN REV:" at 1541.5,-656.17 h60
  text ".PCB_Rev" at 2088,-656.17 h60
  text "REV:" at 2379.5,-656.17 h60
  text ".PRJ_Number" at 3224,-656.17 h60
  text "BOARD #:" at 3769.5,-656.17 h60
  text "PCB VIEWED FROM BOTTOM SIDE" at 6246,-656.17 h60
  text ".TID" at 3224,-859.5 h60
  text "TID #:" at 3769.5,-859.5 h60
  text "TEXAS INSTRUMENTS" at 904.5,-1064.84 h60
  text ".Print_Time" at 2169,-1064.84 h60
  text ".Print_Date" at 2898,-1064.84 h60
  text "GENERATED    :" at 3767.5,-1064.84 h60
  text ".plot_File_Name" at 5440.5,-1064.84 h60
  text "PLOT NAME =" at 6246,-1064.84 h60
M9 Title Sheet:
  drawing of 57 lines, arcs and shapes, not listed
  text "1" at 739.84,8036.5 h70
  text "2" at 3235.5,8036.5 h70
  text "3" at 5724.84,8036.5 h70
  text "4" at 8231.51,8036.5 h70
  text "5" at 10730.5,8036.5 h70
  text "6" at 13235.5,8036.5 h70
  text "A" at -416.5,6893.5 h70
  text "A" at 14383.5,6893.5 h70
  text "B" at -416.5,4513.5 h70
  text "B" at 14383.5,4513.5 h70
  text "C" at -416.5,2138.5 h70
  text "C" at 14383.5,2138.5 h70
  text "PROJECT TITLE:" at 11343.5,277.5 h45
  text ".PRJ_Title" at 11393.5,144.17 h70
  text "DESIGNED FOR:" at 11343.5,-23.5 h45
  text ".PRJ_Customer" at 11393.5,-163.5 h70
  text "D" at -416.5,-231.5 h70
  text "D" at 14383.5,-231.5 h70
  text "FILE NAME:" at 11343.5,-323.5 h45
  text ".PCB_File_Name_No_Path" at 11393.5,-443.5 h70
  text "Texas Instruments (TI) and/or its licensors do not warrant the accuracy or completeness of this specification" at 6374,-605.34 h45
  text "ENGINEER:" at 11343.5,-613.5 h45
  text "LAYOUT BY:" at 12848.5,-613.5 h45
  text "or any information contained therein. TI and/or its licensors do not warrant that this design will meet" at 6329.01,-718 h45
  text ".PRJ_Engineer" at 11393.5,-768.49 h70
  text ".PCB_Layout" at 12899,-768.49 h70
  text "the specifications, will be suitable for your application or fit for any particular purpose, or will operate in" at 6329.01,-830.67 h45
  text ".Layer_Name" at 577,-858.49 h60
  text "ALTIUM DESIGNER VERSION:" at 12848.5,-923.5 h45
  text "an implementation. TI and/or its licensors do not warrant that the design is production worthy. You should" at 6329.01,-943.33 h45
  text "completely validate and test your design implementation to confirm the system functionality for your application." at 6374,-1056 h45
  text ".print_Scale" at 11393.5,-1056.83 h70
  text ".Application_BuildNumber" at 12899,-1056.83 h70
  text "1" at 739.84,-1263.5 h70
  text "2" at 3235.5,-1263.5 h70
  text "3" at 5724.84,-1263.5 h70
  text "4" at 8231.51,-1263.5 h70
  text "5" at 10730.5,-1263.5 h70
  text "6" at 13235.5,-1263.5 h70
M10 Fab Notes:
  drawing of 189 lines, arcs and shapes, not listed
  text "DESIGN INFORMATION" at 12382.02,6356.17 h60
  text "MIN. TRACK WIDTH:" at 11737.46,6224.05 h60
  text "8" at 12833.7,6224.05 h60
  text "MIL" at 12988.46,6224.05 h60
  text "MIN. CLEARANCE:" at 11737.46,6099.92 h60
  text "0.2" at 12773.7,6099.93 h60
  text "mm" at 12988.46,6099.92 h60
  text "MIN. VIA PAD SIZE:" at 11737.46,5975.8 h60
  text "24" at 12803.71,5975.8 h60
  text "MIL" at 12988.46,5975.8 h60
  text "0.05mm (2MIL)" at 12432.46,5845.9 h60
  text "MINIMUM ANNULAR RING" at 11408.23,5837.67 h60
  text "EXTERNAL" at 13140.46,5837.67 h60
  text "PER" at 11608.23,5727.55 h60
  text "IPC-D-275 CLASS 2 LEVEL C" at 11828.23,5727.54 h60
  text "MIL, HOLES" at 13316.46,5627.07 h60
  text "+/-" at 12924,5618.48 h60
  text "+/-" at 13778,5618.48 h60
  text "REGISTRATION TOLERANCES:" at 11408.23,5617.42 h60
  text "METAL" at 12608,5617.42 h60
  text "5" at 13184.2,5617.42 h60
  text "3" at 14017.2,5617.42 h60
  text "MIL" at 14133.46,5617.42 h60
  text "HOLE SIZE TOLERANCE (UNLESS OTHERWISE SPECIFIED):" at 11408.23,5519.1 h60
  text "+/-" at 13778,5516.23 h60
  text "3" at 14017.2,5515.17 h60
  text "MIL" at 14133.46,5515.17 h60
  text "MATERIAL:" at 11333.46,5377.52 h60
  text "FR-4 High Tg" at 12319.9,5249 h60
  text "X" at 12175.46,5241.01 h60
  text "FR-408" at 11754.46,5236.49 h60
  text "OTHER" at 13242.46,5236.49 h60
  text "62 MIL (1.6mm) +/-10%" at 12074.56,5093.46 h60
  text "X" at 11954.46,5091.01 h60
  text "THICKNESS:" at 11408.23,5085.24 h60
  text "OTHER" at 13359.46,5085.24 h60
  text "TOLERANCE:" at 11408.23,4946.92 h60
  text "X" at 12256.46,4946.92 h60
  text "ANSI IPC-6012 TYPE 3 CLASS 2" at 12434.48,4946.92 h60
  text "OTHER +/-" at 12434.46,4802.73 h60
  text "BOW & TWIST:" at 11408.23,4657.54 h60
  text "X" at 12256.46,4657.54 h60
  text "ANSI IPC-6012 TYPE 3 CLASS 2" at 12434.48,4657.54 h60
  text "OTHER +/-" at 12434.46,4510.85 h60
  text "DRILLING:" at 11333.46,4380.23 h60
  text "NC_DRILL FILES" at 13094.46,4275.04 h60
  text "REFERENCE:" at 11408.23,4271.1 h60
  text "X" at 12065.46,4271.01 h60
  text "AS SHOWN" at 12243.46,4271.1 h60
  text "X" at 12966.46,4271.1 h60
  text "OTHER" at 13392.46,4128.85 h60
  text "PTH COPPER THICKNESS:" at 11407.91,4125.32 h60
  text "X" at 12547.14,4125.32 h60
  text "20-30 um" at 12675.14,4125.32 h60
  text "BOARD FINISH:" at 11333.46,3977.73 h60
  text "SILKSCREEN:" at 11488.68,3867.6 h60
  text "X" at 12446.46,3867.6 h60
  text "TOP" at 12563.46,3867.6 h60
  text "X" at 12956.46,3867.6 h60
  text "BOTTOM" at 13074.46,3867.6 h60
  text "SILKSCREEN COLOR:" at 11488.68,3712.41 h60
  text "X" at 12445.46,3712.41 h60
  text "WHITE" at 12563.46,3712.41 h60
  text "OTHER" at 13074.46,3712.41 h60
  text "X" at 12576.46,3568.96 h60
  text "GREEN" at 12694.46,3568.96 h60
  text "OTHER" at 13312.46,3568.96 h60
  text "SOLDER RESIST COLOR:" at 11488.68,3562.1 h60
  text "X" at 12576.46,3414.71 h60
  text "MATTE" at 12694.46,3414.71 h60
  text "SEMI-GLOSS" at 13312,3414.07 h60
  text "IMMERSION GOLD (ENIG)" at 12394.46,3241.94 h60
  text "ENEPIG" at 13732,3234.72 h60
  text "SURFACE FINISH:" at 11333.46,3233.72 h60
  text "X" at 12216.46,3233.72 h60
  text "IMM. TIN/SILVER OR EQUIV" at 11663,3096.4 h60
  text "OTHER" at 13094.46,3092.47 h60
  text "ARRAY/PANEL:" at 11333.46,2937.09 h60
  text "CUT AND TRIM PER M1 BOARD OUTLINE" at 12394.46,2928.87 h60
  text "N.C. ROUTE" at 12394.46,2792.9 h60
  text "X" at 13082.46,2792.9 h60
  text "V. SCORE" at 13260.46,2792.9 h60
  text "CERTIFICATION:" at 11333.46,2663.77 h60
  text "MATERIALS AND WORKMANSHIP FOR ALL PCBS" at 12058.46,2663.77 h60
  text "TO MEET OR EXCEED THE REQUIREMENTS OF:" at 12058.46,2569.71 h60
  text "X" at 11695.97,2441.08 h60
  text "ANSI IPC-A-600F CLASS ->" at 11823.96,2441.08 h60
  text "X" at 13471.97,2441.08 h60
  text "2" at 13581.96,2441.08 h60
  text "1" at 13266.96,2439.58 h60
  text "3" at 13935.96,2439.58 h60
  text "X" at 12507.97,2293.39 h60
  text "RoHS" at 12635.96,2293.39 h60
  text "OTHER" at 13280.36,2293.39 h60
  text "PER ORDER" at 13677.42,2293.39 h60
  text "ALL BOARDS MUST MEET OR EXCEED UL94-V0 REQUIREMENTS." at 11361,2139.57 h60
  text "PCB MUST BEAR THE UL94V-0 UL REGISTERED MATERIAL ID NUMBER" at 11361,2023.5 h60
  text "ADDITIONAL REQUIREMENTS:" at 11333.46,1854.08 h60
  text "MICROSECTION:" at 11408.23,1746.95 h60
  text "YES" at 12313.96,1746.95 h60
  text "REQUIRED" at 13175.46,1602.62 h60
  text "BARE BOARD ELEC. TEST:" at 11408.23,1599.76 h60
  text "NONE" at 12713.96,1599.76 h60
  text "X" at 13057.46,1599.76 h60
  text "PER ORDER" at 13767.46,1599.76 h60
  text "XX MIL VIAS REQUIRE NON-CONDUCTIVE FILL AND PLANARIZE" at 11576.38,1394.82 h59
  text "XX MIL VIAS REQUIRE CONDUCTIVE FILL AND PLANARIZE" at 11584.38,1290.84 h60
  text "OUTER XX MIL TRACES REQUIRE 50 OHM SINGLE-ENDED IMPEDANCE" at 11583.39,1127.46 h58
  text "LAYER 2 & 3 (INNER LAYERS) XX MIL WIDE, XX MIL SPACE / TRACES REQUIRE 100 OHM DIFFERENTIAL IMPEDANCE" at 11575.39,891.74 h60
  text ".Layer_Name" at 577,-858.49 h60
M11 Gerber Information:
  lines w10: -292,-930.17 6308,-930.17 ; -292,-726.83 6310,-726.83 ; -292,-523.5 -292,-1133.5 3713,-1133.5 6310,-1133.5 6310,-523.5 -291.5,-523.5 -291.5,-1133.5 1284,-1133.5 ; 2173,-1133.5 2173,-523.5 ; 3440,-726.83 3440,-523.5 ; 4280,-726.83 4280,-523.5 ; 4902,-1140 4902,-937.17
  text "ALL ARTWORK VIEWED FROM TOP SIDE" at -228.5,-655.67 h60
  text "BOARD #:" at 2248,-655.67 h60
  text ".PRJ_Number" at 2793.5,-655.67 h60
  text "REV:" at 3638,-655.67 h60
  text ".PCB_Rev" at 3929.5,-655.67 h60
  text "SVN REV:" at 4476,-655.67 h60
  text ".VersionControl_RevNumber" at 4982,-655.67 h60
  text "LAYER NAME =" at -228.5,-858.49 h60
  text "TID #:" at 2248,-859 h60
  text ".TID" at 2793.5,-859 h60
  text "PLOT NAME =" at -228.5,-1064.34 h60
  text ".plot_File_Name" at 577,-1064.34 h60
  text "GENERATED    :" at 2250,-1064.34 h60
  text ".Print_Date" at 3119.5,-1064.34 h60
  text ".Print_Time" at 3848.5,-1064.34 h60
  text "TEXAS INSTRUMENTS" at 5113,-1064.34 h60
M12 Stackup:
  drawing of 191 lines, arcs and shapes, not listed
  text "Layer" at 9797.84,7605 h60
  text "Name" at 10207.76,7605 h60
  text "Material" at 11137.5,7605 h60
  text "Thickness" at 11997.27,7605 h60
  text "Constant" at 12647.1,7605 h60
  text "Board Layer Stack" at 13216.96,7605 h60
  text "1" at 9797.84,7485 h60
  text "Top Overlay" at 10207.76,7485 h60
  text "2" at 9797.84,7365 h60
  text "Top Solder" at 10207.76,7365 h60
  text "Solder Resist" at 11137.5,7365 h60
  text "0.40mil" at 11997.27,7365 h60
  text "3.5" at 12647.1,7365 h60
  text "3" at 9797.84,7245 h60
  text "Top Layer" at 10207.76,7245 h60
  text "Copper" at 11137.5,7245 h60
  text "1.40mil" at 11997.27,7245 h60
  text "4" at 9797.84,7125 h60
  text "Dielectric1" at 10207.76,7125 h60
  text "FR-4" at 11137.5,7125 h60
  text "59.20mil" at 11997.27,7125 h60
  text "4.8" at 12647.1,7125 h60
  text "5" at 9797.84,7005 h60
  text "Bottom Layer" at 10207.76,7005 h60
  text "Copper" at 11137.5,7005 h60
  text "1.40mil" at 11997.27,7005 h60
  text "6" at 9797.84,6885 h60
  text "Bottom Solder" at 10207.76,6885 h60
  text "Solder Resist" at 11137.5,6885 h60
  text "0.40mil" at 11997.27,6885 h60
  text "3.5" at 12647.1,6885 h60
  text "7" at 9797.84,6765 h60
  text "Bottom Overlay" at 10207.76,6765 h60
  text ".Layer_Name" at 577,-858.49 h60
M13 Component Bodies Top:
  text ".Layer_Name" at 577,-858.49 h60
M14 Component Bodies Bottom:
  text ".Layer_Name" at 577,-858.49 h60
M15 Courtyards Top:
  text ".Layer_Name" at 577,-858.49 h60
M16 Courtyards Bottom:
  text ".Layer_Name" at 577,-858.49 h60
Drill Drawing:
  circle w10: c5363.63,3332.5 r27.59
  lines w10: 5336.04,2739.21 5391.23,2739.21 5363.63,2684.02 5336.04,2739.21 ; 5336.04,2808.2 5391.23,2808.2 5391.23,2863.39 5336.04,2863.39 5336.04,2808.2 ; 5336.04,2946.17 5349.83,2946.17 5349.83,2932.37 5377.43,2932.37 5377.43,2946.17 5391.23,2946.17 5391.23,2973.76 5377.43,2973.76 5377.43,2987.56 5349.83,2987.56 5349.83,2973.76 5336.04,2973.76 5336.04,2946.17 ; 5336.04,3056.55 5363.63,3070.35 5391.23,3056.55 5377.43,3084.14 5391.23,3111.74 5363.63,3097.94 5336.04,3111.74 5349.83,3084.14 5336.04,3056.55 ; 5336.04,3194.52 5349.83,3194.52 5363.63,3180.72 5377.43,3194.52 5391.23,3194.52 5377.43,3208.32 5391.23,3222.12 5377.43,3222.12 5363.63,3235.91 5349.83,3222.12 5336.04,3222.12 5349.83,3208.32 5336.04,3194.52
  lines w12: 5286,2646.77 8516.52,2646.77 ; 5286,3391.82 8516.52,3391.82 ; 5623.86,2522.59 5623.86,3516 ; 5955.86,2522.59 5955.86,3516 ; 6592.42,2522.59 6592.42,3516 ; 6851.53,2522.59 6851.53,3516 ; 7226.68,2522.59 7226.68,3516 ; 7950.06,2522.59 7950.06,3516 ; 5286,2522.59 8516.52,2522.59 8516.52,3516 5286,3516 5286,2522.59
  text "Symbol" at 5360.51,3429.08 h72
  text "Quantity" at 5661.11,3429.08 h72
  text "Finished Hole Size" at 5993.12,3429.08 h72
  text "Plated" at 6629.67,3429.08 h72
  text "Hole Type" at 6888.78,3429.08 h72
  text "Drill Layer Pair" at 7263.93,3429.08 h72
  text "Hole Tolerance" at 7987.32,3429.08 h72
  text "2" at 5661.11,3304.9 h60
  text "53.94mil (1.370mm)" at 5993.12,3304.9 h60
  text "NPTH" at 6629.67,3304.9 h60
  text "Round" at 6888.78,3304.9 h60
  text "Top Layer - Bottom Layer" at 7263.93,3304.9 h60
  text "4" at 5661.11,3180.72 h60
  text "152.00mil (3.861mm)" at 5993.12,3180.72 h60
  text "NPTH" at 6629.67,3180.72 h60
  text "Round" at 6888.78,3180.72 h60
  text "Top Layer - Bottom Layer" at 7263.93,3180.72 h60
  text "8" at 5661.11,3056.55 h60
  text "7.87mil (0.200mm)" at 5993.12,3056.55 h60
  text "PTH" at 6629.67,3056.55 h60
  text "Round" at 6888.78,3056.55 h60
  text "Top Layer - Bottom Layer" at 7263.93,3056.55 h60
  text "23" at 5661.11,2932.37 h60
  text "15.00mil (0.381mm)" at 5993.12,2932.37 h60
  text "PTH" at 6629.67,2932.37 h60
  text "Round" at 6888.78,2932.37 h60
  text "Top Layer - Bottom Layer" at 7263.93,2932.37 h60
  text "12" at 5661.11,2808.2 h60
  text "40.00mil (1.016mm)" at 5993.12,2808.2 h60
  text "PTH" at 6629.67,2808.2 h60
  text "Round" at 6888.78,2808.2 h60
  text "Top Layer - Bottom Layer" at 7263.93,2808.2 h60
  text "10" at 5661.11,2684.02 h60
  text "50.00mil (1.270mm)" at 5993.12,2684.02 h60
  text "PTH" at 6629.67,2684.02 h60
  text "Round" at 6888.78,2684.02 h60
  text "Top Layer - Bottom Layer" at 7263.93,2684.02 h60
  text "59 Total" at 5661.11,2559.84 h60
  text ".Layer_Name" at 577,-858.49 h60
M17 Embedded Cavity:
  text ".Layer_Name" at 577,-858.49 h60
M18 Embedded Assembly:
  text ".Layer_Name" at 577,-858.49 h60
M19 Embedded Keepout:
  text ".Layer_Name" at 577,-858.49 h60

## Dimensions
0,-400 to 1000,-400 on M2 Board Dimensions
0,0 to 0,1948.82 on M2 Board Dimensions
0,0 to 2785.43,0 on M2 Board Dimensions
